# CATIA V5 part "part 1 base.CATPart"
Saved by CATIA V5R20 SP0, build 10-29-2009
Part number: p1b
Bounding box of the stored display mesh (mm): x 0 to 1500, y -300 to 900, z -1000 to 340
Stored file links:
  C:\Users\khanm\Downloads\Catia Project (1)\Catia Project\part 1 base.CATPart
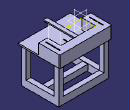
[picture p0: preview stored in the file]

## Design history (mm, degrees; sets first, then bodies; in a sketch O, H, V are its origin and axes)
Body1 (main body)
  Sketch1 on xy-plane, origin (0, 0, 0), H (1, 0, 0), V (0, 1, 0)
    line L1 (30, 0) -> (1470, 0)
    line L2 (1500, 30) -> (1500, 870)
    line L3 (1470, 900) -> (30, 900)
    line L4 (0, 870) -> (0, 30)
    point P1 (1500, 0)
    point P2 (1500, 900)
    arc A1 centre (30, 870) radius 30 from (0, 870) to (30, 900) cw
    arc A2 centre (30, 30) radius 30 from (0, 30) to (30, 0) ccw
    arc A3 centre (1470, 870) radius 30 from (1470, 900) to (1500, 870) cw
    arc A4 centre (1470, 30) radius 30 from (1500, 30) to (1470, 0) cw
    radius A1 = 30
    distance O P1 = 1500
    radius A2 = 30
    distance P1 P2 = 900
    radius A3 = 30
    radius A4 = 30
    horizontal: L1 H, L3 H
    vertical: L2 V, L4 V
    tangency: A1 L4, A1 L3, A2 L4, A2 L1, A3 L3, A3 L2, A4 L2, A4 L1
    coincidence: L4 O, L1 O, L3 P2, L2 P2, L2 P1, L1 P1
  Pad1: profile Sketch1, direction (0, 0, 1), length 40
  Sketch2 on end face of Pad1, origin (0, 0, 40), H (1, 0, 0), V (0, 1, 0)
  Sketch3 on end face of Pad1, origin (0, 0, 40), H (1, 0, 0), V (0, 1, 0)
    line L1 (0, 290.59) -> (0, 870)
    point P1 (0, 290.59)
    line L2 (30, 900) -> (1470, 900)
    line L3 (1500, 870) -> (1500, 290.59)
    reference projected line E1 (0, 870) -> (0, 30) from edge [face of Pad1 from Sketch1.L4 | end face of Pad1]
    reference projected line E2 (1470, 900) -> (30, 900) from edge [face of Pad1 from Sketch1.L3 | end face of Pad1]
    reference projected line E3 (1500, 30) -> (1500, 870) from edge [face of Pad1 from Sketch1.L2 | end face of Pad1]
    arc A1 centre (30, 870) radius 30 from (0, 870) to (30, 900) cw
    arc A2 centre (1470, 870) radius 30 from (1470, 900) to (1500, 870) cw
    line L4 (0, 290.59) -> (250, 290.59)
    line L5 (1500, 290.59) -> (1250, 290.59)
    reference projected line E4 (30, 0) -> (1470, 0) from edge [face of Pad1 from Sketch1.L1 | end face of Pad1]
    reference projected line E5 (30, 0) -> (1470, 0) from edge [face of Pad1 from Sketch1.L1 | end face of Pad1]
    line L6 (250, 290.59) -> (250, 677.61)
    line L7 (250, 677.61) -> (1250, 677.61)
    line L8 (1250, 677.61) -> (1250, 290.59)
    radius A1 = 30
    radius A2 = 30
    length L4 = 250
    length L5 = 250
    distance L4 E4 = 290.59
    distance L5 E5 = 290.59
    length L6 = 387.02
    coincidence: P1 V, L1 E1, L2 E2, L3 E3
    vertical: L1 V, L3 V, L6 V, L8 V
    horizontal: L2 H, L4 H, L5 H, L7 H
    tangency: A1 L1, A1 L2, A2 L2, A2 L3
  Pad2: profile Sketch3, direction (0, 0, 1), length 300
  Sketch4 on end face of Pad2, origin (0, 0, 340), H (1, 0, 0), V (0, 1, 0)
    line L1 (115, 777) -> (135, 777)
    line L2 (135, 777) -> (135, 377)
    line L3 (135, 377) -> (115, 377)
    line L4 (115, 377) -> (115, 777)
    reference projected line E1 (0, 870) -> (0, 290.59) from edge [face of Pad2 | end face of Pad2]
    reference projected line E2 (1470, 900) -> (30, 900) from edge [face of Pad2 | end face of Pad2]
    length L2 = 400
    length L1 = 20
    distance E1 L4 = 115
    distance L1 E2 = 123
    horizontal: L1 H, L3 H
    vertical: L2 V, L4 V
  Pocket1: profile Sketch4, direction (0, 0, -1), length 100
  Plane1: type Offset, RefPlane yz-plane, Offset 750
  Mirror1: of Pocket1, about Plane1
  Sketch5 on end face of Pad1, origin (0, 0, 40), H (1, 0, 0), V (0, 1, 0)
    line L1 (740, 677.61) -> (760, 677.61)
    line L2 (760, 677.61) -> (760, 262.37)
    line L3 (760, 262.37) -> (740, 262.37)
    line L4 (740, 262.37) -> (740, 677.61)
    reference projected line E1 (250, 677.61) -> (1250, 677.61) from edge [face of Pad2 from Sketch3.L7 | end face of Pad2]
    reference projected line E2 (250, 290.59) -> (250, 677.61) from edge [face of Pad2 from Sketch3.L6 | end face of Pad2]
    distance E2 L4 = 490
    length L3 = 20
    length L2 = 415.24
    horizontal: L1 H, L3 H
    vertical: L2 V, L4 V
    coincidence: L1 E1
  Sketch6 on end face of Pad1, origin (0, 0, 40), H (1, 0, 0), V (0, 1, 0)
  Pocket2: profile Sketch5, direction (0, 0, -1), through (limit type 6)
  Sketch7 on face of Pad1 from Sketch1.L1, origin (0, 0, 0), H (1, 0, 0), V (0, 0, 1)
    point P1 (0, 40)
    line L1 (0, 40) -> (1500, 40)
    line L2 (1500, 40) -> (1500, 0)
    line L3 (1500, 0) -> (0, 0)
    line L4 (0, 0) -> (0, 40)
    point P3 (1500, 0)
    reference projected line E1 (30, 40) -> (1470, 40) from edge [face of Pad1 from Sketch1.L1 | end face of Pad1]
    reference projected line E2 (0, 40) -> (0, 340) from edge [face of Pad2 from Sketch3.L4 | face of Pad2]
    reference projected line E3 (1500, 40) -> (1500, 340) from edge [face of Pad2 | face of Pad2 from Sketch3.L5]
    coincidence: P1 V, P3 H, L1 E1, L4 E2, L2 E3
    horizontal: L1 H, L3 H
    vertical: L2 V, L4 V
  Pad3: profile Sketch7, direction (0, -1, 0), length 300
  Sketch8 on face of Pad3 from Sketch7.L2, origin (1500, 0, 0), H (0, 1, 0), V (0, 0, 1)
    line L1 (-10.2967, 40) -> (73.3724, 40)
    line L2 (73.3724, 40) -> (73.3724, 0)
    line L3 (73.3724, 0) -> (-10.2967, 0)
    line L4 (-10.2967, 0) -> (-10.2967, 40)
    point P3 (73.3724, 0)
    reference projected line E1 (30, 0) -> (870, 0) from edge [face of Pad3 | face of Pad2]
    reference projected line E2 (30, 40) -> (870, 40) from edge [face of Pad2 | face of Pad3]
    horizontal: L1 H, L3 H
    vertical: L2 V, L4 V
    coincidence: P3 H, L3 E1, L1 E2
  Pad4: profile Sketch8, direction (-1, 0, 0), up to the existing solid (limit type 2)
  Mirror2: of Pad4, about Plane1
  Sketch9 on face of Pad3, origin (0, 0, 0), H (1, 0, 0), V (0, -1, 0)
    line L1 (31.62, -702.69) -> (166.62, -702.69)
    line L2 (166.62, -702.69) -> (166.62, -837.69)
    line L3 (166.62, -837.69) -> (31.62, -837.69)
    line L4 (31.62, -837.69) -> (31.62, -702.69)
    reference projected line E1 (1470, -900) -> (30, -900) from edge [face of Pad3 | face of Pad2]
    reference projected line E2 (0, 0) -> (0, 300) from edge [face of Pad3 | face of Pad3]
    length L4 = 135
    length L3 = 135
    distance L3 E1 = 62.31
    distance L4 E2 = 31.62
    horizontal: L1 H, L3 H
    vertical: L2 V, L4 V
  Pad5: profile Sketch9, direction (0, 0, -1), length 800
  Mirror3: of Pad5, about Plane1
  Sketch10 on face of Pad3, origin (0, 0, 0), H (1, 0, 0), V (0, -1, 0)
    line L1 (31.62, 237.69) -> (166.62, 237.69)
    line L2 (166.62, 237.69) -> (166.62, 102.69)
    line L3 (166.62, 102.69) -> (31.62, 102.69)
    line L4 (31.62, 102.69) -> (31.62, 237.69)
    reference projected line E1 (0, 0) -> (0, 300) from edge [face of Pad3 | face of Pad3]
    reference projected line E3 (31.62, -837.69) -> (166.62, -837.69) from edge [face of Pad5 from Sketch9.L3 | end face of Pad5]
    reference projected line E4 (1470, -900) -> (30, -900) from edge [face of Pad3 | face of Pad2]
    reference projected line E5 (0, 300) -> (1500, 300) from edge [face of Pad3 | end face of Pad3]
    length L2 = 135
    length L3 = 135
    distance L4 E1 = 31.62
    distance E3 E4 = 62.31 (reference)
    distance E5 L1 = 62.31
    horizontal: L1 H, L3 H
    vertical: L2 V, L4 V
  Pad6: profile Sketch10, direction (0, 0, -1), length 800
  Mirror4: of Pad6, about Plane1
  Sketch11 on face of Mirror3, origin (0, 0, -800), H (1, 0, 0), V (0, -1, 0)
    line L1 (31.62, 237.69) -> (166.62, 237.69)
    line L2 (166.62, 237.69) -> (166.62, -837.69)
    line L3 (166.62, -837.69) -> (31.62, -837.69)
    line L4 (31.62, -837.69) -> (31.62, 237.69)
    reference projected line E1 (31.62, 237.69) -> (31.62, 102.69) from edge [face of Pad6 from Sketch10.L4 | end face of Pad6]
    reference projected line E2 (166.62, 237.69) -> (31.62, 237.69) from edge [face of Pad6 from Sketch10.L1 | end face of Pad6]
    reference projected line E3 (166.62, 102.69) -> (166.62, 237.69) from edge [face of Pad6 from Sketch10.L2 | end face of Pad6]
    reference projected line E4 (31.62, -837.69) -> (166.62, -837.69) from edge [face of Pad5 from Sketch9.L3 | end face of Pad5]
    horizontal: L1 H, L3 H
    vertical: L2 V, L4 V
    coincidence: E1 L4, L1 E2, L2 E3, L3 E4
  Pad7: profile Sketch11, direction (0, 0, -1), length 200
  Mirror5: of Pad7, about Plane1
  Sketch12 on face of Pad7, origin (166.62, 0, 0), H (0, 1, 0), V (0, 0, 1)
    line L1 (702.69, -800) -> (837.69, -800)
    line L2 (837.69, -800) -> (837.69, -1000)
    line L3 (837.69, -1000) -> (702.69, -1000)
    line L4 (702.69, -1000) -> (702.69, -800)
    reference projected line E1 (837.69, 0) -> (837.69, -800) from edge [face of Mirror5 | face of Mirror5]
    reference projected line E2 (-237.69, -1000) -> (837.69, -1000) from edge [face of Mirror5 | face of Mirror5]
    reference projected line E3 (702.69, 0) -> (702.69, -800) from edge [face of Mirror3 | face of Mirror5]
    reference projected line E4 (-102.69, -800) -> (702.69, -800) from edge [face of Mirror5 | face of Mirror5]
    horizontal: L1 H, L3 H
    vertical: L2 V, L4 V
    coincidence: L2 E1, L3 E2, L4 E3, L1 E4
  Pad8: profile Sketch12, direction (1, 0, 0), up to the existing solid (limit type 2)
  Sketch13 on face of Mirror5, origin (1333.38, 0, 0), H (0, -1, 0), V (0, 0, 1)
    line L1 (-374.8, -813.7019) -> (-225.2, -813.7019)
    line L2 (-225.2, -813.7019) -> (-225.2, -972.2253)
    line L3 (-225.2, -972.2253) -> (-374.8, -972.2253)
    line L4 (-374.8, -972.2253) -> (-374.8, -813.7019)
    reference projected line E1 (-837.69, 0) -> (-837.69, -800) from edge [face of Mirror5 | face of Pad7]
    reference projected line E2 (237.69, 0) -> (237.69, -800) from edge [face of Pad7 | face of Pad7]
    distance E1 L4 = 462.89
    distance E2 L2 = 462.89
    horizontal: L1 H, L3 H
    vertical: L2 V, L4 V
  Pad9: profile Sketch13, direction (-1, 0, 0), up to the existing solid (limit type 2)
  Sketch14 on face of Pocket2, origin (0, 677.61, 0), H (1, 0, 0), V (0, 0, 1)
    point P1 (749.4848, 260.6554)
    line L1 (803.1521, 291.8957) -> (803.1521, 229.4152)
    line L2 (803.1521, 229.4152) -> (695.8176, 229.4152)
    line L3 (695.8176, 229.4152) -> (695.8176, 291.8957)
    line L4 (695.8176, 291.8957) -> (803.1521, 291.8957)
  Pad10: profile Sketch14, direction (0, -1, 0), length 950
  Fillet1: radius 45, on edge [face of Pad10 from Sketch14.L3 | end face of Pad10]; edge [face of Pad10 from Sketch14.L1 | end face of Pad10]
  Fillet2: radius 30, on edge [face of Pad10 from Sketch14.L1 | face of Pad10 from Sketch14.L2]; edge [face of Pad10 from Sketch14.L2 | face of Pad10 from Sketch14.L3]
